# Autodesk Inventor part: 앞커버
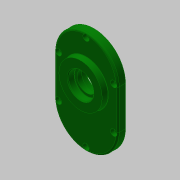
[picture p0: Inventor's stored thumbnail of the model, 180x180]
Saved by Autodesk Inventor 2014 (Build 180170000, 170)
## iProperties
Created: 2016-12
Part Number: 앞커버
Material: 알루미늄 6061
Document SubType Name: Modeling
Designer: mduedu
Density: 2.71 g/cm^3
Mass: 264.838 g
Surface Area: 264.105 cm^2
Volume: 97.726 cm^3
Appearance: 진녹색
Author: mduedu
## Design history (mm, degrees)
sketch "스케치1"
  geometry: L1 (40, -25)-(40, 25); L2 (-40, 25)-(-40, -25); L3 (-40, -25)-(40, 25); L4 (40, -25)-(-40, 25); A1 r 40 centre (0, 25) between (40, 25) and (-40, 25); A2 r 40 centre (0, -25) between (-40, -25) and (40, -25); 1 further point
  constraints: 8 end point, 4 point on circle, 4 tangent, 2 centre point, 2 midpoint, 1 parallel, 1 vertical
  dimensions: "d0" = 130 dimension on A2 A1; "d2" = 80 distance between parallel lines of L1 L2
extrude "돌출1" new body sketch "스케치1" distance "d3" = 10; taper "d4" = 0 deg
sketch "스케치2"
  geometry: C1 r 21 at (0, 11); 1 further point
  constraints: 1 centre point, 1 vertical alignment
  dimensions: "d5" = 42 diameter of C1; "d7" = 11 distance of C1.centre point (0, 0)
extrude "돌출2" join sketch "스케치2" distance "d8" = 7; taper "d9" = 0 deg
sketch "스케치3"
  geometry: C1 r 15 at (0, -33.1); C2 r 21 at (0, 11) reference; 1 further point
  constraints: 1 centre point, 1 vertical alignment
  dimensions: "d10" = 30 diameter of C1; "d71" = 44.1 distance of C1.centre C2.centre
extrude "돌출3" join sketch "스케치3" distance "d12" = 7; taper "d13" = 0 deg
sketch "스케치4"
  geometry: C1 r 28 at (0, 11); A1 r 21 centre (0, 11) between (8.978, -7.984) and (-8.978, -7.984) reference; 1 further point
  constraints: 1 centre point, 1 coincident
  dimensions: "d14" = 56 diameter of C1
extrude "돌출4" join sketch "스케치4" distance "d15" = 7; taper "d16" = -5 deg
hole "구멍1" diameter "d19" = 35; stored, may be unused: countersink angle "d23" = 90 deg, drill point angle "d25" = 0 deg; dims "d17" = 10, "d18" = 10, "d20" = 6, "d21" = 4, "d22" = 2, "d24" = 10
hole "구멍2" diameter "d28" = 22; stored, may be unused: countersink angle "d32" = 90 deg, drill point angle "d34" = 0 deg; dims "d26" = 10, "d27" = 10, "d29" = 6, "d30" = 4, "d31" = 2, "d33" = 7
hole "구멍3" diameter "d37" = 19; stored, may be unused: countersink angle "d41" = 90 deg, drill point angle "d43" = 0 deg; dims "d35" = 10, "d36" = 10, "d38" = 6, "d39" = 4, "d40" = 2, "d42" = 1
hole "구멍4" diameter "d46" = 32; stored, may be unused: countersink angle "d50" = 90 deg, drill point angle "d52" = 0 deg; dims "d44" = 10, "d45" = 10, "d47" = 6, "d48" = 4, "d49" = 2, "d51" = 8
hole "구멍5" diameter "d55" = 25; stored, may be unused: countersink angle "d59" = 90 deg, drill point angle "d61" = 0 deg; dims "d53" = 10, "d54" = 10, "d56" = 6, "d57" = 4, "d58" = 2, "d60" = 8
fillet "모깎기1" dims "d62" = 0.3
fillet "모깎기2" dims "d63" = 2
chamfer "모따기1" distance "d64" = 1; stored, may be unused: second distance "d65" = 2, angle "d66" = 45 deg
fillet "모깎기4" dims "d68" = 2
fillet "모깎기5" dims "d69" = 0.3
fillet "모깎기6" dims "d70" = 2
sketch "스케치5"
  geometry: L1 (-40, 25)-(-40, -25) reference; L2 (40, -25)-(40, 25) reference; L3 (35, 25)-(35, -25); L4 (-35, -25)-(-35, 25); A1 r 40 centre (0, 25) between (40, 25) and (-40, 25) reference; A2 r 40 centre (0, -25) between (-40, -25) and (40, -25) reference; A3 r 35 centre (0, 25) between (35, 25) and (-35, 25); A4 r 35 centre (0, -25) between (-35, -25) and (35, -25); 2 further points
  constraints: 5 point on circle, 4 end point, 2 centre point, 1 vertical alignment, 3 other
  dimensions: "d72" = 5 distance between parallel lines of L2 L3
sketch "스케치7"
  geometry: 1 further point
hole "구멍7" sketch "스케치7" at (0, 60) diameter "d80" = 4.5; stored, may be unused: countersink angle "d84" = 90 deg, drill point angle "d86" = 0 deg; dims "d81" = 6, "d82" = 8, "d83" = 4.6, "d85" = 8
node "솔리드1"
pattern_linear "직사각형 패턴1"
